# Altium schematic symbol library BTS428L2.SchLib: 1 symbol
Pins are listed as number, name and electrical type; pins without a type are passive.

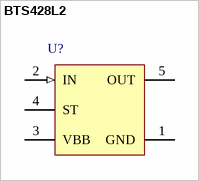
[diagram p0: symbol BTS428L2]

## BTS428L2
designator U?
Smart High-Side Power Switch, 1 Channel, 5.8 A Load Current, -40 to 150 degC, PG-TO252-5-11, Reel, Green; Manufacturer: Infineon; PartNumber: BTS428L2; Channels: 1; Green: TRUE; Group: Automotive Qualified; Load Current (typ): 5.8 A; Ptot (max): 75 W; Recommended Operating Voltage Max.: 41 V; Recommended Operating Voltage Min.: 4.75 V; RON @ 25degreesC: 60 mOhm; RON(max) @ 150degreesC: 120 mOhm; toff (max): 200 us
footprint INF-PG-TO252-5-11_N (DPAK, 5-Leads, Body 6.5x6.12mm, Pitch 1.14mm, IPC Medium Density)
footprint INF-PG-TO252-5-11_L (DPAK, 5-Leads, Body 6.5x6.12mm, Pitch 1.14mm, IPC High Density)
footprint INF-PG-TO252-5-11_M (DPAK, 5-Leads, Body 6.5x6.12mm, Pitch 1.14mm, IPC Low Density)
pins: 1 GND (power) "Logic ground.", 2 IN (in) "Input, activates the power switch in case of logical signal.", 3 VBB (power) "Positive power supply voltage, the tab is shorted to this pin", 4 ST (oc) "Diagnostic feedback", 5 OUT (power) "Output to the load."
